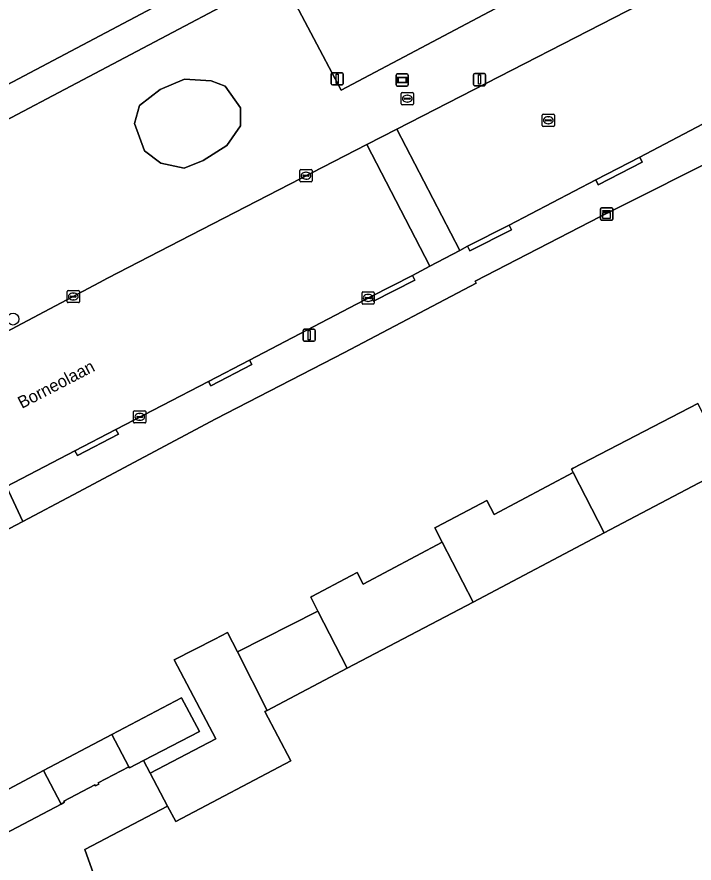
# Model space of a CAD drawing. Extents: x 162879 to 165540, y 384011 to 385181.
# Drawn here: x 163042.9 to 163098.3, y 384052.4 to 384121.6 of the extents above; entities that cross this region are included whole.
import ezdxf

# ---------------------------------------------------------------- set-up
doc = ezdxf.new("R2010")
doc.units = 0
for name, color, linetype in [('IMGEO_Boom', 7, 'Continuous'), ('IMGEO_Brandkraan', 7, 'Continuous'), ('IMGEO_Erf', 7, 'Continuous'), ('IMGEO_Groenvoorziening', 7, 'Continuous'), ('IMGEO_Kast', 7, 'Continuous'), ('IMGEO_Kolk', 7, 'Continuous'), ('IMGEO_Lichtmast', 7, 'Continuous'), ('IMGEO_Openbare_ruimte_label', 7, 'Continuous'), ('IMGEO_Pand', 7, 'Continuous'), ('IMGEO_Rijbaan_lokaal_open', 7, 'Continuous'), ('IMGEO_Rioolput', 7, 'Continuous'), ('IMGEO_Verklikker', 7, 'Continuous'), ('IMGEO_Voetpad_open', 7, 'Continuous')]:
    doc.layers.add(name, color=color, linetype=linetype)

msp = doc.modelspace()

# ---------------------------------------------------------------- linework, layer by layer
at = {"layer": 'IMGEO_Boom'}
msp.add_circle((163042.543, 384096.886), 0.489, dxfattribs=at)
at = {"layer": 'IMGEO_Brandkraan'}
for p, q in [((163074.301, 384114.495), (163074.301, 384115.347)), ((163074.376, 384115.421), (163075.228, 384115.421)), ((163074.56, 384114.915), (163074.56, 384114.927)), ((163074.998, 384114.878), (163074.6, 384114.878)), ((163074.603, 384114.964), (163075.001, 384114.964)), ((163074.789, 384115.201), (163074.814, 384115.201)), ((163075.044, 384114.927), (163075.044, 384114.915)), ((163075.302, 384115.347), (163075.302, 384114.495)), ((163075.228, 384114.421), (163074.376, 384114.421)), ((163074.812, 384114.641), (163074.787, 384114.641))]:
    msp.add_line(p, q, dxfattribs=at)
for points in [[(163074.301, 384114.495), (163074.301, 384115.347)], [(163074.376, 384115.421), (163075.228, 384115.421)], [(163075.302, 384115.347), (163075.302, 384114.495)], [(163075.228, 384114.421), (163074.376, 384114.421)]]:
    msp.add_lwpolyline(points, dxfattribs=at)
for centre, radius, start, end in [((163074.378, 384115.345), 0.0765, 91.55205, 178.44795), ((163074.378, 384115.345), 0.0765, 91.55205, 178.44795), ((163074.6, 384114.924), 0.0403, 85.87752, 175.75265), ((163074.597, 384114.914), 0.0366, 178.93798, 274.71019), ((163075.001, 384114.921), 0.043, 264.86636, 352.45326), ((163075.005, 384114.926), 0.0386, 1.73085, 96.63898), ((163075.226, 384115.345), 0.0765, 1.55205, 88.44795), ((163075.226, 384115.345), 0.0765, 1.55205, 88.44795), ((163074.378, 384114.497), 0.0765, 181.55205, 268.44795), ((163074.378, 384114.497), 0.0765, 181.55205, 268.44795), ((163075.226, 384114.497), 0.0765, 271.55205, 358.44795), ((163075.226, 384114.497), 0.0765, 271.55205, 358.44795)]:
    msp.add_arc(centre, radius, start, end, dxfattribs=at)
for centre, major_axis, ratio, start_param, end_param in [((163074.788, 384114.921), (-0.387, 0.002), 0.722429, 4.712389, 7.853982), ((163074.813, 384114.921), (-0.39, 0.002), 0.717154, 1.570796, 4.712389)]:
    msp.add_ellipse(centre, major_axis=major_axis, ratio=ratio, start_param=start_param, end_param=end_param, dxfattribs=at)
at = {"layer": 'IMGEO_Erf'}
for points in [[(163143.243, 384132.428), (163127.213, 384124.054), (163112.295, 384116.3), (163101.541, 384110.753), (163090.595, 384105.288), (163080.354, 384099.991), (163080.44, 384099.827), (163069.673, 384094.152), (163059.14, 384088.719), (163047.464, 384082.495), (163043.34, 384080.331), (163036.987, 384076.997)], [(163039.382, 384056.954), (163045.027, 384059.933), (163050.632, 384062.891), (163056.325, 384065.896), (163057.794, 384063.144), (163053.225, 384060.756), (163053.758, 384059.737), (163059.138, 384062.549), (163055.729, 384069.01), (163059.057, 384070.701), (163060.1, 384071.231), (163060.907, 384069.644), (163067.485, 384072.989), (163066.9, 384074.142), (163066.988, 384074.189), (163070.17, 384075.872), (163070.685, 384076.146), (163071.186, 384075.2), (163077.664, 384078.631), (163077.042, 384079.804), (163077.203, 384079.889), (163081.296, 384082.049), (163081.899, 384080.908), (163088.381, 384084.329), (163088.232, 384084.612), (163088.368, 384084.683), (163098.556, 384089.986)]]:
    msp.add_lwpolyline(points, dxfattribs=at)
at = {"layer": 'IMGEO_Groenvoorziening'}
for points in [[(163024.815, 384086.721), (163049.609, 384099.879), (163050.264, 384100.227), (163057.094, 384103.745), (163071.502, 384111.166), (163073.953, 384112.428), (163097.961, 384124.794)], [(163085.723, 384124.303), (163069.383, 384115.626), (163064.419, 384125.025), (163037.943, 384111.038)], [(163133.967, 384060.005), (163119.879, 384094.378), (163122.878, 384095.918), (163122.751, 384096.165), (163111.871, 384090.432), (163101.209, 384084.815), (163090.915, 384079.391), (163080.177, 384073.733), (163069.887, 384068.312), (163063.339, 384064.862), (163063.148, 384064.761), (163065.272, 384060.737), (163055.854, 384055.766), (163055.195, 384057.015), (163048.427, 384053.481), (163050.089, 384048.819), (163052.238, 384042.658), (163056.31, 384029.259), (163058.401, 384020.573), (163076.91, 384018.915), (163099.497, 384017.908), (163118.997, 384017.421), (163131.185, 384017.33)], [(163048.427, 384053.481), (163055.195, 384057.015), (163053.758, 384059.737), (163053.225, 384060.756), (163052.078, 384060.156), (163052.027, 384060.254), (163049.515, 384058.928), (163049.567, 384058.831), (163049.284, 384058.681), (163049.232, 384058.779), (163046.703, 384057.444), (163046.755, 384057.346), (163046.474, 384057.197), (163040.82, 384054.214)], [(163016.859, 384057.974), (163012.625, 384055.779), (163006.708, 384052.638), (163004.139, 384051.275), (163002.578, 384050.491), (163003.801, 384048.016), (163000, 384045.696), (162997.514, 384044.178), (163000, 384039.19), (163008.486, 384023.124), (163008.269, 384022.393), (163008.239, 384022.29), (163011.936, 384023.994), (163058.401, 384020.573), (163056.31, 384029.259), (163052.238, 384042.658), (163050.089, 384048.819), (163048.427, 384053.481)]]:
    msp.add_lwpolyline(points, dxfattribs=at)
for points in [[(163054.584, 384115.679), (163052.89, 384114.35), (163052.492, 384112.89), (163053.289, 384110.665), (163054.65, 384109.636), (163056.542, 384109.238), (163058.103, 384109.868), (163060.028, 384111.097), (163061.157, 384112.69), (163061.157, 384114.184), (163059.896, 384115.944), (163058.767, 384116.376), (163056.576, 384116.509)], [(163054.584, 384115.679), (163056.576, 384116.509), (163058.767, 384116.376), (163059.896, 384115.944), (163061.157, 384114.184), (163061.157, 384112.69), (163060.028, 384111.097), (163058.103, 384109.868), (163056.542, 384109.238), (163054.65, 384109.636), (163053.289, 384110.665), (163052.492, 384112.89), (163052.89, 384114.35)]]:
    msp.add_lwpolyline(points, close=True, dxfattribs=at)
at = {"layer": 'IMGEO_Kast'}
for p, q in [((163090.608, 384105.054), (163090.608, 384105.895)), ((163090.608, 384105.895), (163090.608, 384105.054)), ((163090.683, 384105.979), (163091.524, 384105.979)), ((163091.524, 384105.979), (163090.683, 384105.979)), ((163091.608, 384105.904), (163091.608, 384105.063)), ((163091.608, 384105.063), (163091.608, 384105.904)), ((163091.533, 384104.979), (163090.692, 384104.979)), ((163090.692, 384104.979), (163091.533, 384104.979))]:
    msp.add_line(p, q, dxfattribs=at)
for points in [[(163090.803, 384105.769), (163091.403, 384105.769), (163091.403, 384105.684), (163090.803, 384105.684), (163090.803, 384105.769)], [(163090.803, 384105.594), (163091.403, 384105.594), (163091.403, 384105.105), (163090.803, 384105.105), (163090.803, 384105.594)]]:
    msp.add_lwpolyline(points, dxfattribs=at)
msp.add_circle((163090.887, 384105.443), 0.0377, dxfattribs=at)
for centre, start, end in [((163090.686, 384105.901), 92.4484, 184.28452), ((163090.686, 384105.901), 92.4484, 184.28452), ((163091.53, 384105.901), 2.4484, 94.28452), ((163091.53, 384105.901), 2.4484, 94.28452), ((163090.686, 384105.057), 182.4484, 274.28452), ((163090.686, 384105.057), 182.4484, 274.28452), ((163091.53, 384105.057), 272.4484, 4.28452), ((163091.53, 384105.057), 272.4484, 4.28452)]:
    msp.add_arc(centre, 0.0779, start, end, dxfattribs=at)
at = {"layer": 'IMGEO_Kolk'}
for p, q in [((163066.008, 384108.193), (163066.008, 384109.045)), ((163066.083, 384109.119), (163066.935, 384109.119)), ((163066.267, 384108.613), (163066.267, 384108.625)), ((163066.705, 384108.576), (163066.307, 384108.576)), ((163066.31, 384108.662), (163066.708, 384108.662)), ((163066.496, 384108.899), (163066.521, 384108.899)), ((163066.751, 384108.625), (163066.751, 384108.613)), ((163067.009, 384109.045), (163067.009, 384108.193)), ((163066.935, 384108.119), (163066.083, 384108.119)), ((163066.519, 384108.339), (163066.494, 384108.339)), ((163046.972, 384098.304), (163046.972, 384099.156)), ((163047.047, 384099.23), (163047.899, 384099.23)), ((163047.46, 384099.01), (163047.485, 384099.01)), ((163047.973, 384099.156), (163047.973, 384098.304)), ((163071.095, 384098.19), (163071.095, 384099.042)), ((163071.17, 384099.116), (163072.022, 384099.116)), ((163071.583, 384098.896), (163071.608, 384098.896)), ((163072.096, 384099.042), (163072.096, 384098.19)), ((163047.899, 384098.23), (163047.047, 384098.23)), ((163047.231, 384098.724), (163047.231, 384098.736)), ((163047.669, 384098.687), (163047.271, 384098.687)), ((163047.274, 384098.773), (163047.672, 384098.773)), ((163047.483, 384098.45), (163047.458, 384098.45)), ((163047.715, 384098.736), (163047.715, 384098.724)), ((163071.354, 384098.61), (163071.354, 384098.622)), ((163071.792, 384098.573), (163071.394, 384098.573)), ((163071.397, 384098.659), (163071.795, 384098.659)), ((163071.606, 384098.336), (163071.581, 384098.336)), ((163071.838, 384098.622), (163071.838, 384098.61)), ((163072.022, 384098.116), (163071.17, 384098.116)), ((163052.412, 384088.458), (163052.412, 384089.31)), ((163052.487, 384089.384), (163053.339, 384089.384)), ((163052.9, 384089.164), (163052.925, 384089.164)), ((163053.413, 384089.31), (163053.413, 384088.458)), ((163052.671, 384088.878), (163052.671, 384088.89)), ((163053.109, 384088.841), (163052.711, 384088.841)), ((163052.714, 384088.927), (163053.112, 384088.927)), ((163052.923, 384088.604), (163052.898, 384088.604)), ((163053.155, 384088.89), (163053.155, 384088.878)), ((163053.339, 384088.384), (163052.487, 384088.384))]:
    msp.add_line(p, q, dxfattribs=at)
for points in [[(163066.008, 384108.193), (163066.008, 384109.045)], [(163066.083, 384109.119), (163066.935, 384109.119)], [(163067.009, 384109.045), (163067.009, 384108.193)], [(163066.935, 384108.119), (163066.083, 384108.119)], [(163046.972, 384098.304), (163046.972, 384099.156)], [(163047.047, 384099.23), (163047.899, 384099.23)], [(163047.973, 384099.156), (163047.973, 384098.304)], [(163071.095, 384098.19), (163071.095, 384099.042)], [(163071.17, 384099.116), (163072.022, 384099.116)], [(163072.096, 384099.042), (163072.096, 384098.19)], [(163047.899, 384098.23), (163047.047, 384098.23)], [(163072.022, 384098.116), (163071.17, 384098.116)], [(163052.412, 384088.458), (163052.412, 384089.31)], [(163052.487, 384089.384), (163053.339, 384089.384)], [(163053.413, 384089.31), (163053.413, 384088.458)], [(163053.339, 384088.384), (163052.487, 384088.384)]]:
    msp.add_lwpolyline(points, dxfattribs=at)
for centre, radius, start, end in [((163066.085, 384109.043), 0.0765, 91.55205, 178.44795), ((163066.085, 384109.043), 0.0765, 91.55205, 178.44795), ((163066.307, 384108.622), 0.0403, 85.87752, 175.75265), ((163066.304, 384108.612), 0.0366, 178.93798, 274.71019), ((163066.708, 384108.619), 0.043, 264.86636, 352.45326), ((163066.712, 384108.624), 0.0386, 1.73085, 96.63898), ((163066.933, 384109.043), 0.0765, 1.55205, 88.44795), ((163066.933, 384109.043), 0.0765, 1.55205, 88.44795), ((163066.085, 384108.195), 0.0765, 181.55205, 268.44795), ((163066.085, 384108.195), 0.0765, 181.55205, 268.44795), ((163066.933, 384108.195), 0.0765, 271.55205, 358.44795), ((163066.933, 384108.195), 0.0765, 271.55205, 358.44795), ((163047.049, 384099.154), 0.0765, 91.55205, 178.44795), ((163047.049, 384099.154), 0.0765, 91.55205, 178.44795), ((163047.897, 384099.154), 0.0765, 1.55205, 88.44795), ((163047.897, 384099.154), 0.0765, 1.55205, 88.44795), ((163071.172, 384099.04), 0.0765, 91.55205, 178.44795), ((163071.172, 384099.04), 0.0765, 91.55205, 178.44795), ((163072.02, 384099.04), 0.0765, 1.55205, 88.44795), ((163072.02, 384099.04), 0.0765, 1.55205, 88.44795), ((163047.049, 384098.306), 0.0765, 181.55205, 268.44795), ((163047.049, 384098.306), 0.0765, 181.55205, 268.44795), ((163047.271, 384098.733), 0.0403, 85.87752, 175.75265), ((163047.268, 384098.723), 0.0366, 178.93798, 274.71019), ((163047.672, 384098.73), 0.043, 264.86636, 352.45326), ((163047.676, 384098.735), 0.0386, 1.73085, 96.63898), ((163047.897, 384098.306), 0.0765, 271.55205, 358.44795), ((163047.897, 384098.306), 0.0765, 271.55205, 358.44795), ((163071.172, 384098.192), 0.0765, 181.55205, 268.44795), ((163071.172, 384098.192), 0.0765, 181.55205, 268.44795), ((163071.394, 384098.619), 0.0403, 85.87752, 175.75265), ((163071.391, 384098.609), 0.0366, 178.93798, 274.71019), ((163071.795, 384098.616), 0.043, 264.86636, 352.45326), ((163071.799, 384098.621), 0.0386, 1.73085, 96.63898), ((163072.02, 384098.192), 0.0765, 271.55205, 358.44795), ((163072.02, 384098.192), 0.0765, 271.55205, 358.44795), ((163052.489, 384089.308), 0.0765, 91.55205, 178.44795), ((163052.489, 384089.308), 0.0765, 91.55205, 178.44795), ((163053.337, 384089.308), 0.0765, 1.55205, 88.44795), ((163053.337, 384089.308), 0.0765, 1.55205, 88.44795), ((163052.711, 384088.887), 0.0403, 85.87752, 175.75265), ((163052.708, 384088.877), 0.0366, 178.93798, 274.71019), ((163053.112, 384088.884), 0.043, 264.86636, 352.45326), ((163053.116, 384088.889), 0.0386, 1.73085, 96.63898), ((163052.489, 384088.46), 0.0765, 181.55205, 268.44795), ((163052.489, 384088.46), 0.0765, 181.55205, 268.44795), ((163053.337, 384088.46), 0.0765, 271.55205, 358.44795), ((163053.337, 384088.46), 0.0765, 271.55205, 358.44795)]:
    msp.add_arc(centre, radius, start, end, dxfattribs=at)
for centre, major_axis, ratio, start_param, end_param in [((163066.495, 384108.619), (-0.387, 0.002), 0.722429, 4.712389, 7.853982), ((163066.52, 384108.619), (-0.39, 0.002), 0.717154, 1.570796, 4.712389), ((163047.459, 384098.73), (-0.387, 0.002), 0.722429, 4.712389, 7.853982), ((163047.484, 384098.73), (-0.39, 0.002), 0.717154, 1.570796, 4.712389), ((163071.582, 384098.616), (-0.387, 0.002), 0.722429, 4.712389, 7.853982), ((163071.607, 384098.616), (-0.39, 0.002), 0.717154, 1.570796, 4.712389), ((163052.899, 384088.884), (-0.387, 0.002), 0.722429, 4.712389, 7.853982), ((163052.924, 384088.884), (-0.39, 0.002), 0.717154, 1.570796, 4.712389)]:
    msp.add_ellipse(centre, major_axis=major_axis, ratio=ratio, start_param=start_param, end_param=end_param, dxfattribs=at)
at = {"layer": 'IMGEO_Lichtmast'}
for p, q in [((163068.571, 384116.149), (163068.571, 384116.949)), ((163068.571, 384116.949), (163068.571, 384116.149)), ((163068.671, 384117.049), (163069.461, 384117.049)), ((163069.461, 384117.049), (163068.671, 384117.049)), ((163069.561, 384116.949), (163069.561, 384116.149)), ((163069.561, 384116.149), (163069.561, 384116.949)), ((163080.217, 384116.085), (163080.217, 384116.885)), ((163080.217, 384116.885), (163080.217, 384116.085)), ((163080.317, 384116.985), (163081.107, 384116.985)), ((163081.107, 384116.985), (163080.317, 384116.985)), ((163081.207, 384116.885), (163081.207, 384116.085)), ((163081.207, 384116.085), (163081.207, 384116.885)), ((163069.461, 384116.049), (163068.671, 384116.049)), ((163068.671, 384116.049), (163069.461, 384116.049)), ((163081.107, 384115.985), (163080.317, 384115.985)), ((163080.317, 384115.985), (163081.107, 384115.985)), ((163066.272, 384095.165), (163066.272, 384095.965)), ((163066.272, 384095.965), (163066.272, 384095.165)), ((163066.372, 384096.065), (163067.162, 384096.065)), ((163067.162, 384096.065), (163066.372, 384096.065)), ((163067.262, 384095.965), (163067.262, 384095.165)), ((163067.262, 384095.165), (163067.262, 384095.965)), ((163067.162, 384095.065), (163066.372, 384095.065)), ((163066.372, 384095.065), (163067.162, 384095.065))]:
    msp.add_line(p, q, dxfattribs=at)
for points in [[(163068.991, 384116.924), (163069.141, 384116.924), (163069.141, 384116.174), (163068.991, 384116.174), (163068.991, 384116.924)], [(163080.637, 384116.86), (163080.787, 384116.86), (163080.787, 384116.11), (163080.637, 384116.11), (163080.637, 384116.86)], [(163066.692, 384095.94), (163066.842, 384095.94), (163066.842, 384095.19), (163066.692, 384095.19), (163066.692, 384095.94)]]:
    msp.add_lwpolyline(points, dxfattribs=at)
for centre, start, end in [((163068.671, 384116.949), 90, 180), ((163068.671, 384116.949), 90, 180), ((163069.461, 384116.949), 0, 90), ((163069.461, 384116.949), 360, 90), ((163080.317, 384116.885), 90, 180), ((163080.317, 384116.885), 90, 180), ((163081.107, 384116.885), 0, 90), ((163081.107, 384116.885), 360, 90), ((163068.671, 384116.149), 180, 270), ((163068.671, 384116.149), 180, 270), ((163069.461, 384116.149), 270, 0), ((163069.461, 384116.149), 270, 0), ((163080.317, 384116.085), 180, 270), ((163080.317, 384116.085), 180, 270), ((163081.107, 384116.085), 270, 0), ((163081.107, 384116.085), 270, 0), ((163066.372, 384095.965), 90, 180), ((163066.372, 384095.965), 90, 180), ((163067.162, 384095.965), 0, 90), ((163067.162, 384095.965), 360, 90), ((163066.372, 384095.165), 180, 270), ((163066.372, 384095.165), 180, 270), ((163067.162, 384095.165), 270, 0), ((163067.162, 384095.165), 270, 0)]:
    msp.add_arc(centre, 0.1, start, end, dxfattribs=at)
at = {"layer": 'IMGEO_Pand'}
for points in [[(163101.209, 384084.815), (163098.556, 384089.986), (163088.368, 384084.683), (163088.232, 384084.612), (163088.381, 384084.329), (163090.915, 384079.391)], [(163090.915, 384079.391), (163088.381, 384084.329), (163081.899, 384080.908), (163081.296, 384082.049), (163077.203, 384079.889), (163077.042, 384079.804), (163077.664, 384078.631), (163080.177, 384073.733)], [(163077.664, 384078.631), (163071.186, 384075.2), (163070.685, 384076.146), (163070.17, 384075.872), (163066.988, 384074.189), (163066.9, 384074.142), (163067.485, 384072.989), (163069.887, 384068.312), (163080.177, 384073.733)], [(163067.485, 384072.989), (163060.907, 384069.644), (163063.339, 384064.862), (163069.887, 384068.312)], [(163060.907, 384069.644), (163060.1, 384071.231), (163059.057, 384070.701), (163055.729, 384069.01), (163059.138, 384062.549), (163053.758, 384059.737), (163055.195, 384057.015), (163055.854, 384055.766), (163065.272, 384060.737), (163063.148, 384064.761), (163063.339, 384064.862)], [(163057.794, 384063.144), (163056.325, 384065.896), (163050.632, 384062.891), (163052.027, 384060.254), (163052.078, 384060.156), (163053.225, 384060.756)], [(163052.027, 384060.254), (163050.632, 384062.891), (163045.027, 384059.933), (163046.474, 384057.197), (163046.755, 384057.346), (163046.703, 384057.444), (163049.232, 384058.779), (163049.284, 384058.681), (163049.567, 384058.831), (163049.515, 384058.928)], [(163046.474, 384057.197), (163045.027, 384059.933), (163039.382, 384056.954), (163040.769, 384054.312), (163040.82, 384054.214)]]:
    msp.add_lwpolyline(points, close=True, dxfattribs=at)
at = {"layer": 'IMGEO_Rijbaan_lokaal_open'}
for points in [[(163055.571, 384140.093), (163062.549, 384126.9), (163037.712, 384113.762), (163030.742, 384126.945)], [(163104.389, 384115.671), (163111.658, 384119.475), (163115.056, 384121.214), (163116.886, 384122.167), (163111.878, 384131.962), (163105.709, 384128.785), (163103.332, 384127.561), (163103.267, 384127.527), (163097.961, 384124.794), (163073.953, 384112.428), (163079.089, 384102.505), (163079.729, 384102.844), (163083.135, 384104.564), (163090.228, 384108.281), (163093.815, 384110.133), (163101.034, 384113.928)], [(163073.953, 384112.428), (163071.502, 384111.166), (163076.651, 384101.215), (163079.089, 384102.505)]]:
    msp.add_lwpolyline(points, close=True, dxfattribs=at)
for points in [[(163037.943, 384111.038), (163064.419, 384125.025), (163069.383, 384115.626), (163085.723, 384124.303)], [(163058.537, 384091.788), (163061.885, 384093.537), (163071.848, 384098.744), (163075.222, 384100.459), (163076.651, 384101.215), (163071.502, 384111.166), (163057.094, 384103.745), (163050.264, 384100.227), (163049.609, 384099.879), (163024.815, 384086.721), (163028.882, 384078.964)], [(163037.992, 384081.091), (163042.007, 384083.183), (163047.605, 384086.1), (163050.952, 384087.838), (163058.537, 384091.788)]]:
    msp.add_lwpolyline(points, dxfattribs=at)
at = {"layer": 'IMGEO_Rioolput'}
for p, q in [((163085.835, 384112.729), (163085.835, 384113.581)), ((163085.91, 384113.655), (163086.762, 384113.655)), ((163086.323, 384113.435), (163086.348, 384113.435)), ((163086.836, 384113.581), (163086.836, 384112.729)), ((163086.094, 384113.149), (163086.094, 384113.161)), ((163086.532, 384113.112), (163086.134, 384113.112)), ((163086.137, 384113.198), (163086.535, 384113.198)), ((163086.346, 384112.875), (163086.321, 384112.875)), ((163086.578, 384113.161), (163086.578, 384113.149)), ((163086.762, 384112.655), (163085.91, 384112.655))]:
    msp.add_line(p, q, dxfattribs=at)
for points in [[(163085.835, 384112.729), (163085.835, 384113.581)], [(163085.91, 384113.655), (163086.762, 384113.655)], [(163086.836, 384113.581), (163086.836, 384112.729)], [(163086.762, 384112.655), (163085.91, 384112.655)]]:
    msp.add_lwpolyline(points, dxfattribs=at)
for centre, radius, start, end in [((163085.912, 384113.579), 0.0765, 91.55205, 178.44795), ((163085.912, 384113.579), 0.0765, 91.55205, 178.44795), ((163086.76, 384113.579), 0.0765, 1.55205, 88.44795), ((163086.76, 384113.579), 0.0765, 1.55205, 88.44795), ((163085.912, 384112.731), 0.0765, 181.55205, 268.44795), ((163085.912, 384112.731), 0.0765, 181.55205, 268.44795), ((163086.134, 384113.158), 0.0403, 85.87752, 175.75265), ((163086.131, 384113.148), 0.0366, 178.93798, 274.71019), ((163086.535, 384113.155), 0.043, 264.86636, 352.45326), ((163086.539, 384113.16), 0.0386, 1.73085, 96.63898), ((163086.76, 384112.731), 0.0765, 271.55205, 358.44795), ((163086.76, 384112.731), 0.0765, 271.55205, 358.44795)]:
    msp.add_arc(centre, radius, start, end, dxfattribs=at)
for centre, major_axis, ratio, start_param, end_param in [((163086.322, 384113.155), (-0.387, 0.002), 0.722429, 4.712389, 7.853982), ((163086.347, 384113.155), (-0.39, 0.002), 0.717154, 1.570796, 4.712389)]:
    msp.add_ellipse(centre, major_axis=major_axis, ratio=ratio, start_param=start_param, end_param=end_param, dxfattribs=at)
at = {"layer": 'IMGEO_Verklikker'}
for p, q in [((163073.982, 384116.948), (163074.772, 384116.948)), ((163074.772, 384116.948), (163073.982, 384116.948)), ((163073.882, 384116.048), (163073.882, 384116.848)), ((163073.882, 384116.848), (163073.882, 384116.048)), ((163074.872, 384116.848), (163074.872, 384116.048)), ((163074.872, 384116.048), (163074.872, 384116.848)), ((163074.772, 384115.948), (163073.982, 384115.948)), ((163073.982, 384115.948), (163074.772, 384115.948))]:
    msp.add_line(p, q, dxfattribs=at)
for points in [[(163073.983, 384116.68), (163074.771, 384116.68), (163074.771, 384116.216), (163073.983, 384116.216), (163073.983, 384116.68)], [(163074.048, 384116.615), (163074.048, 384116.281), (163074.706, 384116.281), (163074.706, 384116.615), (163074.048, 384116.615)]]:
    msp.add_lwpolyline(points, dxfattribs=at)
for centre, start, end in [((163073.982, 384116.848), 90, 180), ((163073.982, 384116.848), 90, 180), ((163074.772, 384116.848), 0, 90), ((163074.772, 384116.848), 360, 90), ((163073.982, 384116.048), 180, 270), ((163073.982, 384116.048), 180, 270), ((163074.772, 384116.048), 270, 0), ((163074.772, 384116.048), 270, 0)]:
    msp.add_arc(centre, 0.1, start, end, dxfattribs=at)
at = {"layer": 'IMGEO_Voetpad_open'}
for points in [[(163062.549, 384126.9), (163055.571, 384140.093), (163030.742, 384126.945), (163037.712, 384113.762)], [(163093.815, 384110.133), (163090.228, 384108.281), (163090.42, 384107.882), (163094.007, 384109.734)], [(163083.135, 384104.564), (163079.729, 384102.844), (163079.919, 384102.478), (163083.325, 384104.198)], [(163075.222, 384100.459), (163071.848, 384098.744), (163072.042, 384098.361), (163075.416, 384100.076)], [(163061.885, 384093.537), (163058.537, 384091.788), (163058.727, 384091.418), (163062.075, 384093.167)], [(163050.952, 384087.838), (163047.605, 384086.1), (163047.823, 384085.722), (163051.17, 384087.46)]]:
    msp.add_lwpolyline(points, close=True, dxfattribs=at)
for points in [[(163101.034, 384113.928), (163093.815, 384110.133), (163094.007, 384109.734), (163090.42, 384107.882), (163090.228, 384108.281), (163083.135, 384104.564), (163083.325, 384104.198), (163079.919, 384102.478), (163079.729, 384102.844), (163079.089, 384102.505), (163076.651, 384101.215), (163075.222, 384100.459), (163075.416, 384100.076), (163072.042, 384098.361), (163071.848, 384098.744), (163061.885, 384093.537), (163062.075, 384093.167), (163058.727, 384091.418), (163058.537, 384091.788), (163050.952, 384087.838), (163051.17, 384087.46), (163047.823, 384085.722), (163047.605, 384086.1), (163042.007, 384083.183), (163043.34, 384080.331), (163047.464, 384082.495), (163059.14, 384088.719), (163069.673, 384094.152), (163080.44, 384099.827), (163080.354, 384099.991), (163090.595, 384105.288), (163101.541, 384110.753)], [(163035.595, 384079.67), (163036.987, 384076.997), (163043.34, 384080.331), (163042.007, 384083.183)]]:
    msp.add_lwpolyline(points, dxfattribs=at)

# ---------------------------------------------------------------- texts
at = {"layer": 'IMGEO_Openbare_ruimte_label'}
msp.add_text('Borneolaan', height=1, rotation=27.46223, dxfattribs=at).set_placement((163043.264, 384089.529))

doc.saveas('drawing.dxf')
